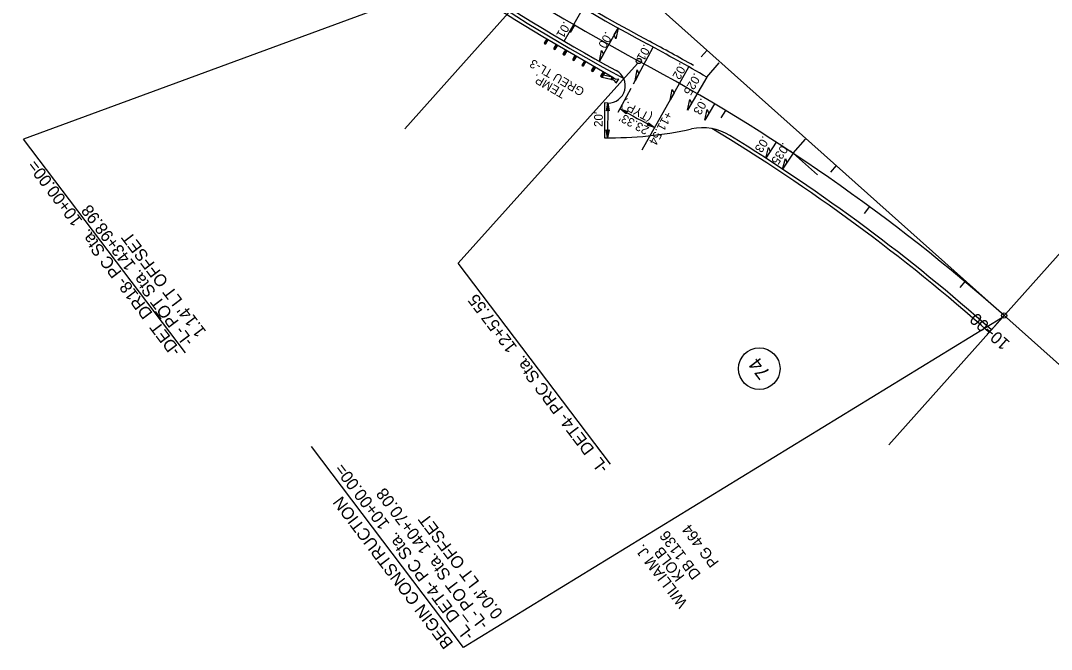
# Model space of a CAD drawing. Extents: x 473658 to 481584, y 489119 to 506230.
# Drawn here: x 476451 to 477047, y 500198 to 500561 of the extents above; entities that cross this region are included whole.
import ezdxf

# ---------------------------------------------------------------- set-up
doc = ezdxf.new("R2010")
doc.units = 0
for name, color, linetype in [('Default', 7, 'Continuous'), ('Exist Horizontal Alignment', 7, 'Continuous'), ('Prop Dimension', 7, 'Continuous'), ('Prop EOT', 7, 'Continuous'), ('Prop Guardrail', 7, 'Continuous'), ('Prop Guardrail Anchor Unit CELL', 7, 'Continuous'), ('Prop Horizontal Alignment', 7, 'Continuous'), ('Prop Horizontal Alignment Station Label', 7, 'Continuous'), ('Prop Horizontal Alignment Tick Label', 7, 'Continuous'), ('Prop Horizontal Alignment Tick Large', 7, 'Continuous'), ('Prop Horizontal Alignment Tick Small', 7, 'Continuous'), ('Prop Paved Shoulder', 7, 'Continuous'), ('Prop Superelevation  Arrow CELL', 7, 'Continuous'), ('Prop Superelevation Label', 7, 'Continuous'), ('Scratch_Level_5', 7, 'Continuous'), ('Scratch_Level_9', 7, 'Continuous'), ('Sheet Plan And Profile CELL', 7, 'Continuous')]:
    doc.layers.add(name, color=color, linetype=linetype)

msp = doc.modelspace()

# ---------------------------------------------------------------- linework, layer by layer
at = {"layer": 'Default'}
msp.add_line((476877.94, 500360.13), (476877.94, 500360.13), dxfattribs=at)
msp.add_circle((476877.94, 500360.13), 12, dxfattribs=at)
at = {"layer": 'Exist Horizontal Alignment'}
for points in [[(476789.73, 500508.9), (476790.54, 500513.4), (476791.31, 500508.87), (476790.51, 500509.45)], [(476791.2, 500497.89), (476790.39, 500493.4), (476789.63, 500497.93), (476790.42, 500497.35)]]:
    msp.add_lwpolyline(points, close=True, dxfattribs=at)
at = {"layer": 'Prop Dimension'}
msp.add_line((476790.54, 500513.4), (476790.39, 500493.4), dxfattribs=at)
at = {"layer": 'Prop EOT'}
for p, q in [((476788.67, 500513.49), (476788.52, 500493.42)), ((476790.54, 500513.4), (476788.67, 500513.49))]:
    msp.add_line(p, q, dxfattribs=at)
for centre, radius, start, end in [((477327.21, 501507.62), 1089, 218.24077, 241.8577), ((477327.21, 501507.62), 1111, 218.24077, 241.40091), ((476289.55, 499567.71), 1111, 59.84865, 61.8577), ((476790.61, 500523.4), 10, 269.58263, 61.40091), ((476791.99, 500711.88), 218.48, 269.09084, 282.38657), ((476845.29, 500469.18), 30, 58.34701, 102.38657), ((476289.55, 499567.71), 1089, 48.4381, 58.34701)]:
    msp.add_arc(centre, radius, start, end, dxfattribs=at)
at = {"layer": 'Prop Guardrail'}
msp.add_arc((477327.21, 501507.62), 1115, 218.24077, 239.00479, dxfattribs=at)
at = {"layer": 'Prop Guardrail Anchor Unit CELL'}
for p, q in [((476753.02, 500551.83), (476793.43, 500528.32)), ((476755.22, 500550.56), (476753.71, 500547.96)), ((476755.33, 500548.76), (476753.71, 500547.96)), ((476753.71, 500547.96), (476754.58, 500547.46)), ((476754.47, 500549.26), (476756.09, 500550.05)), ((476754.47, 500549.26), (476755.33, 500548.76)), ((476754.58, 500547.46), (476754.47, 500549.26)), ((476756.09, 500550.05), (476754.58, 500547.46)), ((476755.22, 500550.56), (476756.09, 500550.05)), ((476755.33, 500548.76), (476755.22, 500550.56)), ((476756.09, 500550.05), (476755.33, 500548.76)), ((476760.67, 500547.39), (476759.13, 500544.75)), ((476759.9, 500546.07), (476761.53, 500546.88)), ((476759.9, 500546.07), (476760.76, 500545.56)), ((476760, 500544.25), (476759.9, 500546.07)), ((476761.53, 500546.88), (476760, 500544.25)), ((476760.67, 500547.39), (476760.76, 500545.56)), ((476760.76, 500545.56), (476759.13, 500544.75)), ((476759.13, 500544.75), (476760, 500544.25)), ((476766.11, 500544.22), (476764.58, 500541.58)), ((476766.21, 500542.4), (476764.58, 500541.58)), ((476764.58, 500541.58), (476765.45, 500541.08)), ((476765.35, 500542.9), (476766.98, 500543.71)), ((476765.35, 500542.9), (476766.21, 500542.4)), ((476765.45, 500541.08), (476765.35, 500542.9)), ((476766.98, 500543.71), (476765.45, 500541.08)), ((476766.11, 500544.22), (476766.21, 500542.4)), ((476771.56, 500541.05), (476770.03, 500538.42)), ((476770.8, 500539.74), (476772.42, 500540.55)), ((476772.42, 500540.55), (476770.9, 500537.92)), ((476771.56, 500541.05), (476772.42, 500540.55)), ((476771.56, 500541.05), (476771.66, 500539.23)), ((476771.66, 500539.23), (476770.03, 500538.42)), ((476770.03, 500538.42), (476770.9, 500537.92)), ((476770.8, 500539.74), (476771.66, 500539.23)), ((476770.9, 500537.92), (476770.8, 500539.74)), ((476777.01, 500537.88), (476775.43, 500535.17)), ((476777.08, 500536.02), (476775.43, 500535.17)), ((476775.43, 500535.17), (476776.29, 500534.66)), ((476776.22, 500536.52), (476777.87, 500537.38)), ((476776.22, 500536.52), (476777.08, 500536.02)), ((476776.29, 500534.66), (476776.22, 500536.52)), ((476777.87, 500537.38), (476776.29, 500534.66)), ((476777.01, 500537.88), (476777.08, 500536.02)), ((476782.45, 500534.71), (476780.94, 500532.12)), ((476781.7, 500533.41), (476783.32, 500534.21)), ((476783.32, 500534.21), (476781.81, 500531.61)), ((476782.45, 500534.71), (476782.56, 500532.91)), ((476782.56, 500532.91), (476780.94, 500532.12)), ((476780.94, 500532.12), (476781.81, 500531.61)), ((476781.7, 500533.41), (476782.56, 500532.91)), ((476781.81, 500531.61), (476781.7, 500533.41)), ((476787.9, 500531.54), (476786.36, 500528.89)), ((476787.99, 500529.71), (476786.36, 500528.89)), ((476786.36, 500528.89), (476787.22, 500528.39)), ((476787.13, 500530.22), (476788.76, 500531.04)), ((476787.13, 500530.22), (476787.99, 500529.71)), ((476787.22, 500528.39), (476787.13, 500530.22)), ((476788.76, 500531.04), (476787.22, 500528.39)), ((476787.22, 500528.39), (476792.24, 500527.28)), ((476787.9, 500531.54), (476787.99, 500529.71)), ((476787.99, 500529.71), (476793, 500528.57)), ((476793, 500528.57), (476792.24, 500527.28)), ((476793.11, 500526.77), (476793, 500528.57)), ((476793.12, 500527.71), (476793.42, 500528.24)), ((476793.42, 500528.24), (476795.21, 500527.24)), ((476793.86, 500528.07), (476792.24, 500527.28)), ((476792.24, 500527.28), (476792.68, 500527.02)), ((476792.24, 500527.28), (476793.11, 500526.77)), ((476792.82, 500527.17), (476793.12, 500527.71)), ((476794.61, 500526.18), (476792.82, 500527.17)), ((476793.86, 500528.07), (476793.11, 500526.77)), ((476795.22, 500524.85), (476794.61, 500526.18)), ((476795.21, 500527.24), (476796.66, 500527.42)), ((476796.66, 500527.42), (476795.22, 500524.85))]:
    msp.add_line(p, q, dxfattribs=at)
at = {"layer": 'Prop Horizontal Alignment'}
msp.add_line((477070.66, 500345.01), (476711.11, 500665.95), dxfattribs=at)
for centre, start, end in [((477327.21, 501507.62), 218.24077, 241.8577), ((476289.55, 499567.71), 48.4381, 61.8577)]:
    msp.add_arc(centre, 1100, start, end, dxfattribs=at)
at = {"layer": 'Prop Horizontal Alignment Station Label'}
for p, q in [((476772.09, 500609.96), (476453.22, 500492.62)), ((476807.67, 500536.34), (476704.2, 500420.98)), ((476546.66, 500369.19), (476453.22, 500492.62)), ((476792.01, 500304.97), (476704.2, 500420.98)), ((477018.33, 500389.65), (476707.18, 500199.21)), ((476707.18, 500199.21), (476619.42, 500315.16))]:
    msp.add_line(p, q, dxfattribs=at)
for centre in [(476808.38, 500537.67), (477019.32, 500390.77)]:
    msp.add_circle(centre, 1.5, dxfattribs=at)
at = {"layer": 'Prop Horizontal Alignment Tick Large'}
msp.add_line((477019.32, 500390.77), (477014.02, 500384.79), dxfattribs=at)
at = {"layer": 'Prop Horizontal Alignment Tick Small'}
for p, q in [((476771.33, 500558.41), (476768.81, 500554.1)), ((476847.82, 500543.91), (476844.49, 500540.18)), ((476858.41, 500509.2), (476855.83, 500504.92)), ((476922.43, 500477.32), (476919.1, 500473.59)), ((476941.56, 500453.65), (476938.6, 500449.62)), ((476997.03, 500410.73), (476993.7, 500407))]:
    msp.add_line(p, q, dxfattribs=at)
at = {"layer": 'Prop Paved Shoulder'}
for centre, radius, start, end in [((477327.21, 501507.62), 1087, 218.24077, 241.8577), ((477327.21, 501507.62), 1113, 218.24077, 241.70868), ((476289.55, 499567.71), 1113, 60.3599, 61.8577), ((476289.55, 499567.71), 1087, 48.4381, 58.92217)]:
    msp.add_arc(centre, radius, start, end, dxfattribs=at)
at = {"layer": 'Prop Superelevation  Arrow CELL'}
for points in [[(476796.4, 500556.75), (476795.22, 500550.54), (476794.15, 500552.71)], [(476785.68, 500537.54), (476786.86, 500543.75), (476787.93, 500541.58)], [(476806.31, 500526.3), (476807.39, 500532.53), (476808.5, 500530.37)], [(476826.52, 500515.12), (476827.74, 500521.33), (476828.8, 500519.15)], [(476836.54, 500509.37), (476837.82, 500515.56), (476838.86, 500513.37)], [(476801.16, 500507.2), (476797.57, 500510.02), (476801.93, 500508.57), (476801.04, 500508.14)], [(476846.5, 500503.52), (476847.85, 500509.7), (476848.86, 500507.49)], [(476813.94, 500502.09), (476817.54, 500499.27), (476813.17, 500500.72), (476814.06, 500501.15)], [(476881.75, 500481.62), (476883.33, 500487.74), (476884.26, 500485.5)], [(476891.4, 500475.29), (476893.05, 500481.4), (476893.95, 500479.15)]]:
    msp.add_lwpolyline(points, close=True, dxfattribs=at)
at = {"layer": 'Prop Superelevation Label'}
for p, q in [((476765.23, 500549.24), (476776.36, 500568.22)), ((476785.68, 500537.54), (476796.4, 500556.75)), ((476805.36, 500524.54), (476816.75, 500545.66)), ((476810.25, 500486.41), (476837.37, 500534.26)), ((476847.59, 500528.4), (476836.54, 500509.37)), ((476796.51, 500508.13), (476803.99, 500522)), ((476852.12, 500512.97), (476846.5, 500503.52)), ((476887.73, 500490.85), (476881.75, 500481.62)), ((476897.48, 500484.46), (476891.4, 500475.29))]:
    msp.add_line(p, q, dxfattribs=at)
msp.add_arc((477370.55, 501550.7), 1187.99, 241.16201, 242.25725, dxfattribs=at)
at = {"layer": 'Scratch_Level_5'}
for p, q in [((476847.59, 500528.39), (476854.86, 500536.59)), ((476897.48, 500484.46), (476904.6, 500492.49)), ((476896, 500485.76), (476911.61, 500472.03))]:
    msp.add_line(p, q, dxfattribs=at)
at = {"layer": 'Scratch_Level_9'}
msp.add_line((476952.76, 500316.21), (477085.94, 500465.41), dxfattribs=at)
at = {"layer": 'Sheet Plan And Profile CELL'}
msp.add_line((476673.33, 500498.6), (476873.11, 500722.41), dxfattribs=at)

# ---------------------------------------------------------------- texts
at = {"layer": 'Default'}
for s, height, p in [('74', 8, (476884.72, 500357.79)), ('DB 1136 ', 6.25, (476844.52, 500241.37)), ('PG 464', 6.25, (476854.94, 500248.33)), ('WILLIAM J. ', 6.25, (476836.85, 500224.91)), ('KOLB', 6.25, (476835.1, 500240.19))]:
    msp.add_text(s, height=height, rotation=127.12364, dxfattribs=at).set_placement(p)
at = {"layer": 'Prop Dimension'}
msp.add_text("20'", height=5, rotation=89.58263, dxfattribs=at).set_placement((476787.55, 500499.61))
at = {"layer": 'Prop Guardrail Anchor Unit CELL'}
for s, p in [('GREU TL-3', (476777.52, 500521.42)), ('TEMP. ', (476766.6, 500520.17))]:
    msp.add_text(s, height=5, rotation=149.90975, dxfattribs=at).set_placement(p)
at = {"layer": 'Prop Horizontal Alignment Station Label'}
for s, rotation, p in [('-DET_DR18- PC Sta.  10+00.00=', 127.12364, (476544.34, 500370.54)), ('-L- POT Sta. 143+98.98', 127.12364, (476551.63, 500376.05)), ("1.14' LT OFFSET", 127.12364, (476558.91, 500381.56)), ('-L_DET4- PRC Sta.  12+57.55', 127.15371, (476791.24, 500302.91)), ('-L_DET4- PC Sta.  10+00.00=', 127.15371, (476713.57, 500206.25)), ('-L- POT Sta. 140+70.08', 127.15371, (476721.94, 500212.59)), ('BEGIN CONSTRUCTION', 127.15371, (476701.61, 500201.69)), ("0.04' LT OFFSET", 127.15371, (476730.31, 500218.94))]:
    msp.add_text(s, height=7, rotation=rotation, dxfattribs=at).set_placement(p)
at = {"layer": 'Prop Horizontal Alignment Tick Label'}
msp.add_text('10+00', height=7, rotation=138.4381, dxfattribs=at).set_placement((477023.09, 500375.41))
at = {"layer": 'Prop Superelevation Label'}
for s, rotation, p in [('.01', 239.61316, (476765.24, 500560.89)), ('.00', 240.82835, (476789.31, 500555)), ('.01', 241.67186, (476811.42, 500547.75)), ('.02', 240.45667, (476832.19, 500537)), ('.025', 239.84881, (476840.51, 500531.15)), ('(TYP.)', 151.69136, (476816.63, 500506.47)), ('.03', 239.24103, (476844.38, 500516.6)), ("23.33'", 151.69136, (476814.73, 500499.22)), ('+11.54', 241.69136, (476823.88, 500509.1)), ('.03', 237.05746, (476880.13, 500494.78)), ('.035', 236.45315, (476891.74, 500490.94))]:
    msp.add_text(s, height=5, rotation=rotation, dxfattribs=at).set_placement(p)

doc.saveas('drawing.dxf')
